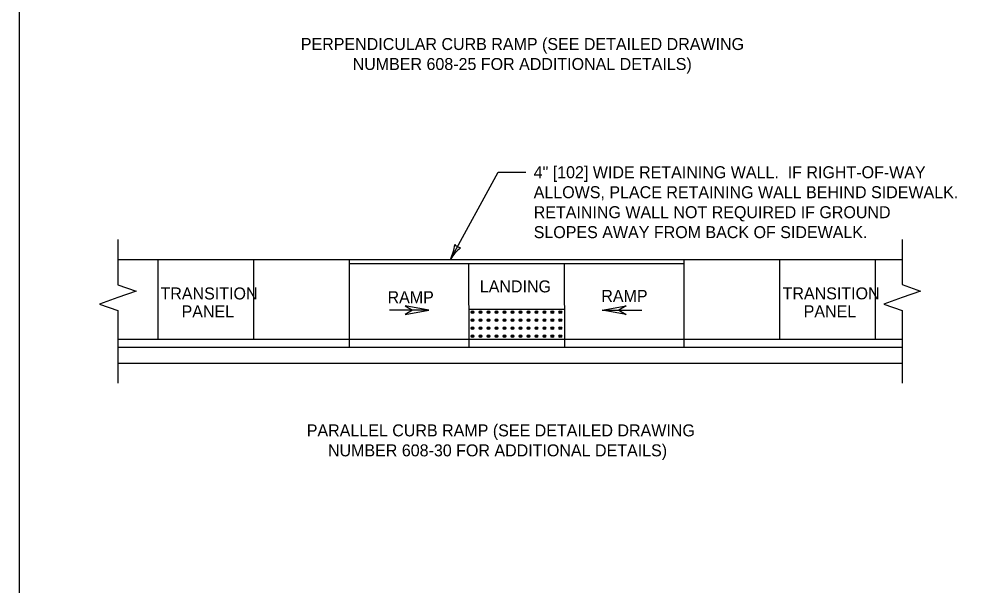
# Model space of a CAD drawing. Extents: x 49991.4 to 50021, y 49987.6 to 50011.4.
# Drawn here: x 50009.737 to 50014.53, y 50002.573 to 50005.41 of the extents above; entities that cross this region are included whole.
import ezdxf

# ---------------------------------------------------------------- set-up
doc = ezdxf.new("R2010")
doc.units = 0
for name, color, linetype in [('Level 1', 7, 'Continuous'), ('Level 2', 7, 'Continuous'), ('Level 3', 7, 'Continuous'), ('Level 6', 7, 'Continuous')]:
    doc.layers.add(name, color=color, linetype=linetype)

msp = doc.modelspace()

# ---------------------------------------------------------------- linework, layer by layer
at = {"layer": 'Level 1'}
for p, q in [((50010.2317, 50004.2064), (50014.1601, 50004.2066)), ((50010.4317, 50004.2064), (50010.4319, 50003.8069)), ((50010.9108, 50004.2064), (50010.911, 50003.8069)), ((50011.3901, 50004.2064), (50011.39, 50003.7671)), ((50011.3903, 50004.1864), (50013.0673, 50004.1864)), ((50011.989, 50004.1864), (50011.9892, 50003.7672)), ((50012.4682, 50004.1864), (50012.4683, 50003.7672)), ((50013.0671, 50004.2063), (50013.0671, 50003.7673)), ((50013.5463, 50004.2063), (50013.5465, 50003.8071)), ((50014.0255, 50004.2065), (50014.0257, 50003.8073)), ((50011.9891, 50003.9572), (50012.4683, 50003.9572)), ((50010.232, 50003.8074), (50014.1601, 50003.807)), ((50010.232, 50003.767), (50014.1601, 50003.7674)), ((50010.2317, 50003.6873), (50014.1601, 50003.6873))]:
    msp.add_line(p, q, dxfattribs=at)
msp.add_lwpolyline([(50020.9378, 50008.1646), (50009.7374, 50008.1646), (50009.7374, 49999.8856), (50020.9378, 49999.8856)], close=True, dxfattribs=at)
msp.add_lwpolyline([(50020.9378, 50008.1646), (50009.7374, 50008.1646), (50009.7374, 49999.8856), (50020.9378, 49999.8856)], close=True, dxfattribs=at)
for centre, radius in [((50012.0082, 50003.9423), 0.00675), ((50012.0082, 50003.9423), 0.00375), ((50012.0482, 50003.9423), 0.00675), ((50012.0482, 50003.9423), 0.00375), ((50012.0882, 50003.9423), 0.00675), ((50012.0882, 50003.9423), 0.00375), ((50012.1282, 50003.9423), 0.00675), ((50012.1282, 50003.9423), 0.00375), ((50012.1682, 50003.9423), 0.00675), ((50012.1682, 50003.9423), 0.00375), ((50012.2082, 50003.9423), 0.00675), ((50012.2082, 50003.9423), 0.00375), ((50012.2482, 50003.9423), 0.00675), ((50012.2482, 50003.9423), 0.00375), ((50012.2882, 50003.9423), 0.00675), ((50012.2882, 50003.9423), 0.00375), ((50012.3282, 50003.9423), 0.00675), ((50012.3282, 50003.9423), 0.00375), ((50012.3682, 50003.9423), 0.00675), ((50012.3682, 50003.9423), 0.00375), ((50012.4082, 50003.9423), 0.00675), ((50012.4082, 50003.9423), 0.00375), ((50012.4482, 50003.9423), 0.00675), ((50012.4482, 50003.9423), 0.00375), ((50012.0082, 50003.9023), 0.00675), ((50012.0082, 50003.9023), 0.00375), ((50012.0482, 50003.9023), 0.00675), ((50012.0482, 50003.9023), 0.00375), ((50012.0882, 50003.9023), 0.00675), ((50012.0882, 50003.9023), 0.00375), ((50012.1282, 50003.9023), 0.00675), ((50012.1282, 50003.9023), 0.00375), ((50012.1682, 50003.9023), 0.00675), ((50012.1682, 50003.9023), 0.00375), ((50012.2082, 50003.9023), 0.00675), ((50012.2082, 50003.9023), 0.00375), ((50012.2482, 50003.9023), 0.00675), ((50012.2482, 50003.9023), 0.00375), ((50012.2882, 50003.9023), 0.00675), ((50012.2882, 50003.9023), 0.00375), ((50012.3282, 50003.9023), 0.00675), ((50012.3282, 50003.9023), 0.00375), ((50012.3682, 50003.9023), 0.00675), ((50012.3682, 50003.9023), 0.00375), ((50012.4082, 50003.9023), 0.00675), ((50012.4082, 50003.9023), 0.00375), ((50012.4482, 50003.9023), 0.00675), ((50012.4482, 50003.9023), 0.00375), ((50012.0082, 50003.8623), 0.00675), ((50012.0082, 50003.8223), 0.00675), ((50012.0082, 50003.8623), 0.00375), ((50012.0482, 50003.8623), 0.00675), ((50012.0482, 50003.8223), 0.00675), ((50012.0482, 50003.8623), 0.00375), ((50012.0882, 50003.8623), 0.00675), ((50012.0882, 50003.8223), 0.00675), ((50012.0882, 50003.8623), 0.00375), ((50012.1282, 50003.8623), 0.00675), ((50012.1282, 50003.8223), 0.00675), ((50012.1282, 50003.8623), 0.00375), ((50012.1682, 50003.8623), 0.00675), ((50012.1682, 50003.8223), 0.00675), ((50012.1682, 50003.8623), 0.00375), ((50012.2082, 50003.8623), 0.00675), ((50012.2082, 50003.8223), 0.00675), ((50012.2082, 50003.8623), 0.00375), ((50012.2482, 50003.8623), 0.00675), ((50012.2482, 50003.8223), 0.00675), ((50012.2482, 50003.8623), 0.00375), ((50012.2882, 50003.8623), 0.00675), ((50012.2882, 50003.8223), 0.00675), ((50012.2882, 50003.8623), 0.00375), ((50012.3282, 50003.8623), 0.00675), ((50012.3282, 50003.8223), 0.00675), ((50012.3282, 50003.8623), 0.00375), ((50012.3682, 50003.8623), 0.00675), ((50012.3682, 50003.8223), 0.00675), ((50012.3682, 50003.8623), 0.00375), ((50012.4082, 50003.8623), 0.00675), ((50012.4082, 50003.8223), 0.00675), ((50012.4082, 50003.8623), 0.00375), ((50012.4482, 50003.8623), 0.00675), ((50012.4482, 50003.8223), 0.00675), ((50012.4482, 50003.8623), 0.00375), ((50012.0082, 50003.8223), 0.00375), ((50012.0482, 50003.8223), 0.00375), ((50012.0882, 50003.8223), 0.00375), ((50012.1282, 50003.8223), 0.00375), ((50012.1682, 50003.8223), 0.00375), ((50012.2082, 50003.8223), 0.00375), ((50012.2482, 50003.8223), 0.00375), ((50012.2882, 50003.8223), 0.00375), ((50012.3282, 50003.8223), 0.00375), ((50012.3682, 50003.8223), 0.00375), ((50012.4082, 50003.8223), 0.00375), ((50012.4482, 50003.8223), 0.00375)]:
    msp.add_circle(centre, radius, dxfattribs=at)
at = {"layer": 'Level 3'}
for p, q in [((50011.8975, 50004.2065), (50012.1361, 50004.6433)), ((50012.1361, 50004.6433), (50012.2748, 50004.6433)), ((50011.7903, 50003.9524), (50011.5917, 50003.9524)), ((50012.6584, 50003.9524), (50012.8571, 50003.9524))]:
    msp.add_line(p, q, dxfattribs=at)
for points in [[(50011.6712, 50003.9316), (50011.7903, 50003.9524), (50011.6712, 50003.9737), (50011.7075, 50003.9525)], [(50012.7775, 50003.9316), (50012.6584, 50003.9524), (50012.7775, 50003.9737), (50012.7412, 50003.9525)]]:
    msp.add_lwpolyline(points, close=True, dxfattribs=at)
for centre, radius, start, end in [((50011.6877, 50004.308), 0.233, 334.1831, 353.4329), ((50012.088, 50004.092), 0.2223, 128.8118, 148.9953), ((50011.9589, 50004.319), 0.0548, 223.4946, 259.2169)]:
    msp.add_arc(centre, radius, start, end, dxfattribs=at)
at = {"layer": 'Level 6'}
for p, q in [((50010.2317, 50004.3064), (50010.2317, 50004.0803)), ((50014.1601, 50004.3069), (50014.1601, 50004.0806)), ((50010.2317, 50004.0803), (50010.3231, 50004.0479)), ((50014.1601, 50004.0806), (50014.2515, 50004.0482)), ((50010.3231, 50004.0479), (50010.2317, 50004.0155)), ((50014.2515, 50004.0482), (50014.1601, 50004.0158)), ((50010.2317, 50004.0155), (50010.1403, 50003.9831)), ((50010.1403, 50003.9831), (50010.2317, 50003.9507)), ((50014.1601, 50004.0158), (50014.0687, 50003.9834)), ((50014.0687, 50003.9834), (50014.1601, 50003.951)), ((50010.2317, 50003.9507), (50010.2317, 50003.5873)), ((50014.1601, 50003.951), (50014.1601, 50003.5876))]:
    msp.add_line(p, q, dxfattribs=at)

# ---------------------------------------------------------------- texts
at = {"layer": 'Level 2'}
for s, p in [('PERPENDICULAR CURB RAMP (SEE DETAILED DRAWING', (50011.1484, 50005.2551)), ('NUMBER 608-25 FOR ADDITIONAL DETAILS)', (50011.4079, 50005.1551)), ('4" [102] WIDE RETAINING WALL.  IF RIGHT-OF-WAY', (50012.3148, 50004.6133)), ('ALLOWS, PLACE RETAINING WALL BEHIND SIDEWALK.', (50012.3148, 50004.5133)), ('RETAINING WALL NOT REQUIRED IF GROUND', (50012.3148, 50004.4133)), ('SLOPES AWAY FROM BACK OF SIDEWALK.', (50012.3148, 50004.3133)), ('TRANSITION', (50010.4456, 50004.0064)), ('LANDING', (50012.0449, 50004.0418)), ('TRANSITION', (50013.5616, 50004.0069)), ('RAMP', (50011.5828, 50003.9877)), ('RAMP', (50012.6534, 50003.9938)), ('PANEL ', (50010.551, 50003.9164)), ('PANEL ', (50013.6671, 50003.9169)), ('PARALLEL CURB RAMP (SEE DETAILED DRAWING', (50011.1782, 50003.3209)), ('NUMBER 608-30 FOR ADDITIONAL DETAILS)', (50011.2843, 50003.2209))]:
    msp.add_text(s, height=0.06, dxfattribs=at).set_placement(p)

doc.saveas('drawing.dxf')
